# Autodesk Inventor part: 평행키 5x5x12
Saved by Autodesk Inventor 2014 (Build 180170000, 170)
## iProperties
Created: 2024-05
Part Number: 평행키 5x5x12
Material: 일반
Document SubType Name: Modeling
Designer: dg
Density: 1 g/cm^3
Appearance: 기본값
Author: dg
Author: jhkim
Description: 키 및 해당 키홈
Creation Date: 2024-05-07
Sending System: Autodesk Inventor 2025
Preprocessor: ST-DEVELOPER v20
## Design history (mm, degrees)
node "평행키 5x5x121"
body "Solid1"
node "기준1"
